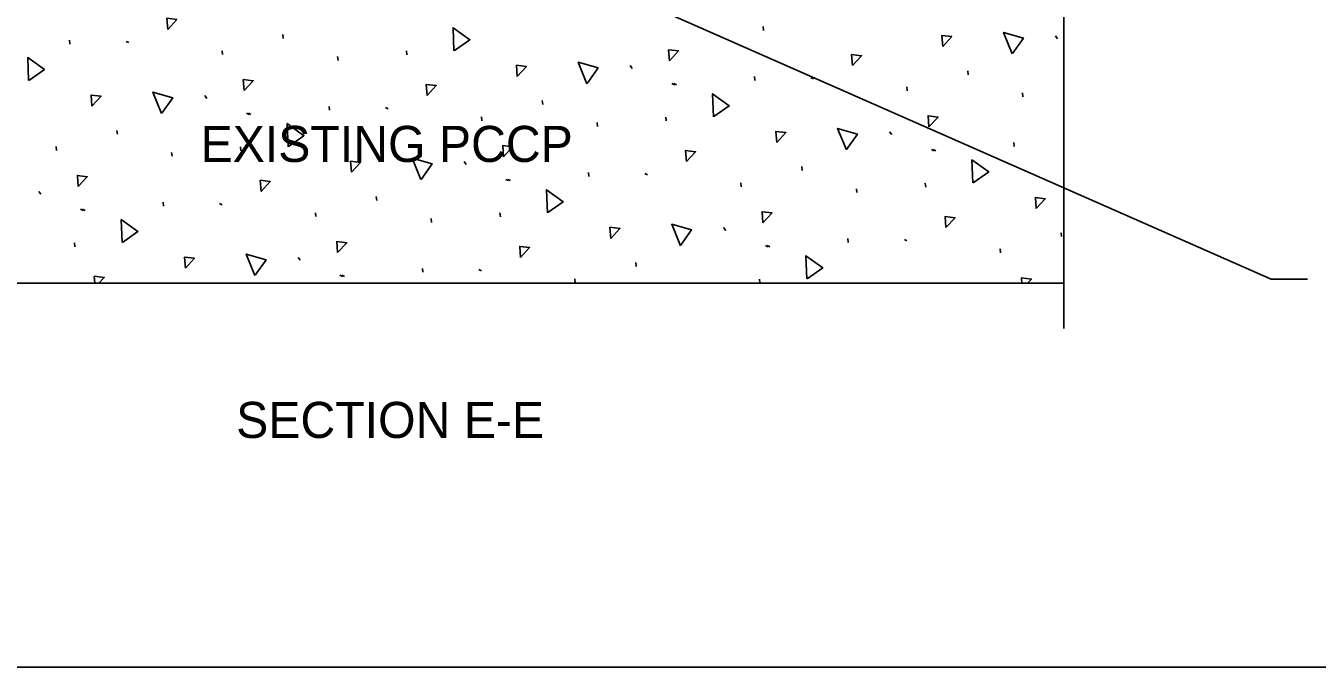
# Model space of a CAD drawing. Extents: x 49991.4 to 50021, y 49987.6 to 50011.4.
# Drawn here: x 50003.117 to 50005.984, y 49987.799 to 49989.221 of the extents above; entities that cross this region are included whole.
import ezdxf

# ---------------------------------------------------------------- set-up
doc = ezdxf.new("R2010")
doc.units = 0
for name, color, linetype in [('Level 1', 7, 'Continuous'), ('Level 2', 7, 'Continuous'), ('Level 3', 7, 'Continuous'), ('Level 4', 7, 'Continuous'), ('Level 6', 7, 'Continuous')]:
    doc.layers.add(name, color=color, linetype=linetype)

msp = doc.modelspace()

# ---------------------------------------------------------------- linework, layer by layer
at = {"layer": 'Level 1'}
msp.add_line((50002.5169, 49988.6501), (50005.421, 49988.6501), dxfattribs=at)
msp.add_lwpolyline([(49999.3835, 49998.9992), (50016.7501, 49998.9992), (50016.7501, 49987.7988), (49999.3835, 49987.7988)], close=True, dxfattribs=at)
at = {"layer": 'Level 3'}
msp.add_line((50005.8817, 49988.6593), (50005.9617, 49988.6593), dxfattribs=at)
msp.add_lwpolyline([(50005.8817, 49988.6593), (50004.366, 49989.3265)], dxfattribs=at)
at = {"layer": 'Level 4'}
for p, q in [((50004.7544, 49989.2104), (50004.7535, 49989.2191)), ((50003.2153, 49989.1801), (50003.2144, 49989.1888)), ((50003.3398, 49989.1864), (50003.3456, 49989.1836)), ((50003.6888, 49989.193), (50003.6878, 49989.2017)), ((50005.4027, 49989.1989), (50005.4075, 49989.1924)), ((50003.5537, 49989.1571), (50003.5527, 49989.1658)), ((50003.8102, 49989.1442), (50003.8093, 49989.1529)), ((50003.9631, 49989.1565), (50003.9622, 49989.1652)), ((50004.4585, 49989.1327), (50004.4633, 49989.1263)), ((50004.7353, 49989.0997), (50004.7343, 49989.1084)), ((50004.8598, 49989.106), (50004.8655, 49989.1032)), ((50005.2087, 49989.1126), (50005.2078, 49989.1213)), ((50003.5144, 49989.0666), (50003.5191, 49989.0601)), ((50004.5514, 49989.0932), (50004.5571, 49989.0903)), ((50004.5555, 49989.0932), (50004.5612, 49989.0903)), ((50005.0736, 49989.0767), (50005.0727, 49989.0854)), ((50005.3302, 49989.0638), (50005.3293, 49989.0725)), ((50003.7911, 49989.0336), (50003.7902, 49989.0423)), ((50003.9156, 49989.0399), (50003.9214, 49989.037)), ((50004.2645, 49989.0465), (50004.2636, 49989.0552)), ((50003.6072, 49989.027), (50003.613, 49989.0242)), ((50003.6113, 49989.027), (50003.617, 49989.0242)), ((50004.1295, 49989.0105), (50004.1285, 49989.0192)), ((50004.5389, 49989.0099), (50004.538, 49989.0186)), ((50003.3204, 49988.9804), (50003.3195, 49988.9891)), ((50004.386, 49988.9977), (50004.3851, 49989.0064)), ((50005.0343, 49988.9862), (50005.0391, 49988.9797)), ((50003.1853, 49988.9444), (50003.1844, 49988.9531)), ((50003.5947, 49988.9438), (50003.5938, 49988.9525)), ((50005.311, 49988.9532), (50005.3101, 49988.9619)), ((50003.4419, 49988.9316), (50003.4409, 49988.9402)), ((50005.1272, 49988.9466), (50005.1329, 49988.9438)), ((50005.1313, 49988.9466), (50005.137, 49988.9438)), ((50004.0902, 49988.92), (50004.0949, 49988.9136)), ((50004.3669, 49988.887), (50004.3659, 49988.8957)), ((50004.4914, 49988.8933), (50004.4972, 49988.8905)), ((50004.8403, 49988.8999), (50004.8394, 49988.9086)), ((50004.183, 49988.8805), (50004.1887, 49988.8776)), ((50004.1871, 49988.8805), (50004.1928, 49988.8776)), ((50004.7052, 49988.864), (50004.7043, 49988.8727)), ((50005.1147, 49988.8634), (50005.1138, 49988.8721)), ((50003.146, 49988.8539), (50003.1507, 49988.8474)), ((50003.8962, 49988.8338), (50003.8952, 49988.8425)), ((50004.9618, 49988.8511), (50004.9609, 49988.8598)), ((50003.2388, 49988.8143), (50003.2446, 49988.8115)), ((50003.2429, 49988.8144), (50003.2487, 49988.8115)), ((50003.4227, 49988.8209), (50003.4218, 49988.8296)), ((50003.5472, 49988.8272), (50003.553, 49988.8243)), ((50003.7611, 49988.7978), (50003.7601, 49988.8065)), ((50004.0177, 49988.785), (50004.0167, 49988.7937)), ((50004.1705, 49988.7973), (50004.1696, 49988.806)), ((50004.666, 49988.7735), (50004.6707, 49988.767)), ((50005.4161, 49988.7534), (50005.4152, 49988.7621)), ((50003.2264, 49988.7311), (50003.2254, 49988.7398)), ((50004.7588, 49988.7339), (50004.7645, 49988.7311)), ((50004.7629, 49988.7339), (50004.7686, 49988.7311)), ((50004.9427, 49988.7405), (50004.9417, 49988.7492)), ((50005.0672, 49988.7468), (50005.073, 49988.7439)), ((50005.281, 49988.7174), (50005.2801, 49988.7261)), ((50003.7218, 49988.7074), (50003.7265, 49988.7009)), ((50004.472, 49988.6872), (50004.471, 49988.6959)), ((50003.8146, 49988.6678), (50003.8204, 49988.6649)), ((50003.8187, 49988.6678), (50003.8244, 49988.665)), ((50003.9985, 49988.6743), (50003.9976, 49988.683)), ((50004.123, 49988.6806), (50004.1288, 49988.6778)), ((50004.3369, 49988.6513), (50004.3359, 49988.66)), ((50004.7463, 49988.6507), (50004.7454, 49988.6594))]:
    msp.add_line(p, q, dxfattribs=at)
for points in [[(50003.4321, 49989.213), (50003.4303, 49989.2376), (50003.4523, 49989.2349), (50003.4321, 49989.213)], [(50004.0676, 49989.1656), (50004.0657, 49989.2168), (50004.1028, 49989.19), (50004.0684, 49989.166)], [(50005.1524, 49989.175), (50005.1505, 49989.1995), (50005.1726, 49989.1969), (50005.1524, 49989.175)], [(50005.3069, 49989.1587), (50005.2876, 49989.2062), (50005.3316, 49989.1936), (50005.3075, 49989.1594)], [(50004.546, 49989.1434), (50004.5441, 49989.1679), (50004.5662, 49989.1653), (50004.546, 49989.1434)], [(50004.9521, 49989.1326), (50004.9502, 49989.1572), (50004.9723, 49989.1545), (50004.9521, 49989.1326)], [(50003.1235, 49989.0994), (50003.1216, 49989.1506), (50003.1586, 49989.1238), (50003.1242, 49989.0999)], [(50004.2082, 49989.1088), (50004.2064, 49989.1334), (50004.2284, 49989.1307), (50004.2082, 49989.1088)], [(50004.3627, 49989.0925), (50004.3434, 49989.14), (50004.3874, 49989.1275), (50004.3633, 49989.0932)], [(50003.6018, 49989.0772), (50003.5999, 49989.1018), (50003.622, 49989.0991), (50003.6018, 49989.0772)], [(50003.2641, 49989.0427), (50003.2622, 49989.0673), (50003.2842, 49989.0646), (50003.2641, 49989.0427)], [(50003.4185, 49989.0264), (50003.3992, 49989.0739), (50003.4432, 49989.0613), (50003.4191, 49989.0271)], [(50004.0079, 49989.0665), (50004.006, 49989.091), (50004.0281, 49989.0884), (50004.0079, 49989.0665)], [(50004.6434, 49989.019), (50004.6415, 49989.0702), (50004.6786, 49989.0434), (50004.6442, 49989.0195)], [(50005.1218, 49988.9968), (50005.1199, 49989.0214), (50005.142, 49989.0187), (50005.1218, 49988.9968)], [(50003.6992, 49988.9529), (50003.6974, 49989.0041), (50003.7344, 49988.9773), (50003.7, 49988.9533)], [(50004.784, 49988.9623), (50004.7822, 49988.9868), (50004.8042, 49988.9842), (50004.784, 49988.9623)], [(50004.9385, 49988.946), (50004.9192, 49988.9935), (50004.9632, 49988.9809), (50004.9391, 49988.9467)], [(50004.1776, 49988.9307), (50004.1757, 49988.9552), (50004.1978, 49988.9526), (50004.1776, 49988.9307)], [(50003.9943, 49988.8799), (50003.975, 49988.9273), (50004.019, 49988.9148), (50003.9949, 49988.8805)], [(50004.5837, 49988.9199), (50004.5818, 49988.9445), (50004.6039, 49988.9418), (50004.5837, 49988.9199)], [(50005.2192, 49988.8725), (50005.2173, 49988.9237), (50005.2544, 49988.8968), (50005.22, 49988.8729)], [(50003.8399, 49988.8962), (50003.838, 49988.9207), (50003.86, 49988.9181), (50003.8399, 49988.8962)], [(50003.2334, 49988.8645), (50003.2316, 49988.8891), (50003.2536, 49988.8864), (50003.2334, 49988.8645)], [(50003.6395, 49988.8538), (50003.6377, 49988.8784), (50003.6597, 49988.8757), (50003.6395, 49988.8538)], [(50004.275, 49988.8063), (50004.2732, 49988.8575), (50004.3102, 49988.8307), (50004.2758, 49988.8068)], [(50005.3598, 49988.8157), (50005.358, 49988.8403), (50005.38, 49988.8376), (50005.3598, 49988.8157)], [(50004.7534, 49988.7841), (50004.7515, 49988.8087), (50004.7736, 49988.806), (50004.7534, 49988.7841)], [(50003.3309, 49988.7402), (50003.329, 49988.7914), (50003.366, 49988.7646), (50003.3316, 49988.7406)], [(50004.5701, 49988.7333), (50004.5508, 49988.7808), (50004.5948, 49988.7682), (50004.5707, 49988.734)], [(50005.1595, 49988.7734), (50005.1576, 49988.7979), (50005.1797, 49988.7953), (50005.1595, 49988.7734)], [(50004.4156, 49988.7496), (50004.4138, 49988.7742), (50004.4358, 49988.7715), (50004.4156, 49988.7496)], [(50003.8092, 49988.718), (50003.8074, 49988.7425), (50003.8294, 49988.7399), (50003.8092, 49988.718)], [(50004.2153, 49988.7072), (50004.2135, 49988.7318), (50004.2355, 49988.7291), (50004.2153, 49988.7072)], [(50003.4715, 49988.6835), (50003.4696, 49988.708), (50003.4916, 49988.7054), (50003.4715, 49988.6835)], [(50003.6259, 49988.6672), (50003.6067, 49988.7146), (50003.6506, 49988.7021), (50003.6265, 49988.6679)], [(50004.8508, 49988.6598), (50004.8489, 49988.711), (50004.886, 49988.6842), (50004.8516, 49988.6602)], [(50003.2705, 49988.6501), (50003.2693, 49988.6657), (50003.2913, 49988.663), (50003.2794, 49988.6501)], [(50005.3282, 49988.6501), (50005.3273, 49988.6621), (50005.3494, 49988.6595), (50005.3407, 49988.6501)]]:
    msp.add_lwpolyline(points, dxfattribs=at)
at = {"layer": 'Level 6'}
msp.add_line((50005.421, 49989.6914), (50005.421, 49988.5501), dxfattribs=at)

# ---------------------------------------------------------------- texts
at = {"layer": 'Level 2'}
for s, p in [('EXISTING PCCP', (50003.5051, 49988.919)), ('SECTION E-E', (50003.5841, 49988.307))]:
    msp.add_text(s, height=0.08, dxfattribs=at).set_placement(p)

doc.saveas('drawing.dxf')
